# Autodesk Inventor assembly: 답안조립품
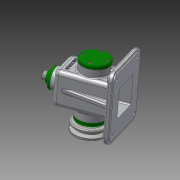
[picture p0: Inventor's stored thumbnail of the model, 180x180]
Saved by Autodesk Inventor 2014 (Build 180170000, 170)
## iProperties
Created: 2016-06
Part Number: 답안조립품
Document SubType Name: Assembly
Designer: user
Author: user
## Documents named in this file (19)
- C:\Users\user\Desktop\Manufacturing2급-박현숙\답안조립품.iam
- C:\Users\user\Desktop\Manufacturing2급-박현숙\본체.ipt
- C:\Users\user\Desktop\Manufacturing2급-박현숙\편심축.ipt
- C:\Users\user\Desktop\Manufacturing2급-박현숙\와셔.ipt
- C:\Users\user\Desktop\Manufacturing2급-박현숙\멈춤링 15 x 1.ipt
- C:\Users\user\Desktop\Manufacturing2급-박현숙\베어링 15 x 35 x 11.ipt
- C:\Users\user\Desktop\Manufacturing2급-박현숙\뒤커버.ipt
- C:\Users\user\Desktop\Manufacturing2급-박현숙\앞커버.ipt
- C:\Users\user\Desktop\Manufacturing2급-박현숙\V-벨트풀리.ipt
- C:\Users\user\Desktop\Manufacturing2급-박현숙\상부부시.ipt
- C:\Users\user\Desktop\Manufacturing2급-박현숙\슬라이드바.ipt
- C:\Users\user\Desktop\Manufacturing2급-박현숙\오일실 15 25 7.ipt
- C:\Users\user\Desktop\Manufacturing2급-박현숙\키 5 x 5 x 14.ipt
- C:\Users\user\Desktop\Manufacturing2급-박현숙\볼트 M6 x 12.ipt
- C:\Users\user\Desktop\Manufacturing2급-박현숙\고정핀.ipt
- C:\Users\user\Desktop\Manufacturing2급-박현숙\링크.ipt
- C:\Users\user\Desktop\Manufacturing2급-박현숙\멈춤링 6 x 5.ipt
- C:\Users\user\Desktop\Manufacturing2급-박현숙\볼트 M4 x 10.ipt
- C:\Users\user\Desktop\Manufacturing2급-박현숙\볼트 M3 x 8.ipt
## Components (15 placed, 5 different names)
1. V-벨트풀리:1 — Mate:56, Mate:57, Mate:58
2. ISO 4018 M6 x 12:1 — Mate:39, Mate:40
3. 고정핀:1 — Mate:27, Mate:28, Insert:4, Insert:5, Mate:29
4. ISO 4762 M4 x 10:1 — Mate:41, Mate:42
5. ISO 4762 M4 x 10:2
6. ISO 4762 M4 x 10:3
7. ISO 4762 M4 x 10:4
8. ISO 4762 M4 x 10:5 — Mate:59, Mate:60
9. ISO 4762 M4 x 10:6
10. ISO 4762 M4 x 10:7
11. ISO 4762 M4 x 10:8
12. ISO 4762 M3 x 8:1 — Mate:61, Mate:62
13. ISO 4762 M3 x 8:2
14. ISO 4762 M3 x 8:3
15. ISO 4762 M3 x 8:4
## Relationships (16: Mate 14, Insert 2)
- Mate:27: 고정핀:1
- Mate:28: 고정핀:1
- Insert:4: 고정핀:1
- Insert:5: 고정핀:1
- Mate:29: 고정핀:1
- Mate:39: ISO 4018 M6 x 12:1
- Mate:40: ISO 4018 M6 x 12:1
- Mate:41: ISO 4762 M4 x 10:1
- Mate:42: ISO 4762 M4 x 10:1
- Mate:56: V-벨트풀리:1
- Mate:57: V-벨트풀리:1
- Mate:58: V-벨트풀리:1
- Mate:59: ISO 4762 M4 x 10:5
- Mate:60: ISO 4762 M4 x 10:5
- Mate:61: ISO 4762 M3 x 8:1
- Mate:62: ISO 4762 M3 x 8:1
